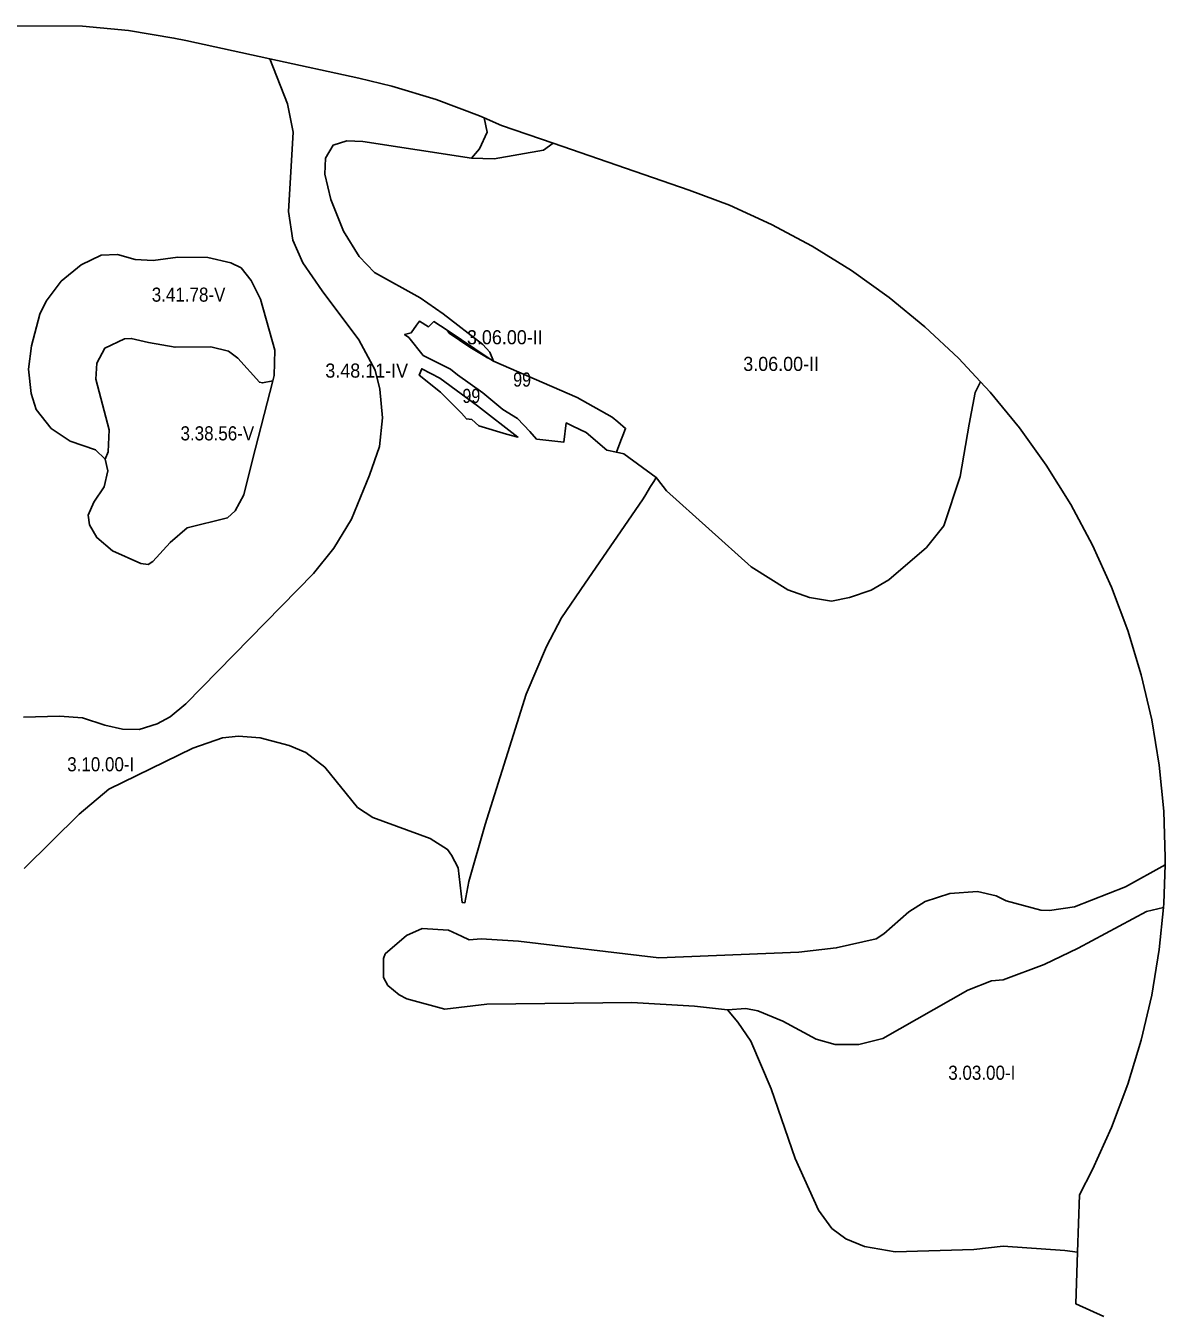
# Model space of a CAD drawing. Extents: x -591496 to -585489, y -1120610 to -1115685.
# Drawn here: x -587628 to -586013, y -1117681 to -1115858 of the extents above; entities that cross this region are included whole.
import ezdxf

# ---------------------------------------------------------------- set-up
doc = ezdxf.new("R2010")
doc.units = 0
doc.header["$LTSCALE"] = 8
doc.layers.add('40', color=7, linetype='Continuous', lineweight=25)
doc.layers.add('41', color=7, linetype='Continuous')

msp = doc.modelspace()

# ---------------------------------------------------------------- linework, layer by layer
at = {"layer": '40'}
for points in [[(-587669.707, -1115858.407), (-587547.277, -1115858.921), (-587482.154, -1115865.335), (-587417.59, -1115875.995), (-587400.616, -1115879.524), (-587281.831, -1115905.301), (-587256.5, -1115969), (-587248.5, -1116009), (-587255.5, -1116121.5), (-587249, -1116162), (-587235, -1116194.5), (-587207.5, -1116234), (-587155.5, -1116303.5), (-587132.5, -1116346.5), (-587126, -1116373.5), (-587122, -1116414), (-587126.5, -1116454.5), (-587140.5, -1116495), (-587166, -1116557.5), (-587191, -1116598.5), (-587220, -1116634.5), (-587400.5, -1116819), (-587423, -1116837.5), (-587441.5, -1116847.5), (-587467, -1116855.5), (-587490.5, -1116855), (-587515.5, -1116849.5), (-587547, -1116839), (-587579.5, -1116836.5), (-587630.5, -1116838)], [(-587630.5, -1116838), (-587579.5, -1116836.5), (-587547, -1116839), (-587515.5, -1116849.5), (-587490.5, -1116855), (-587467, -1116855.5), (-587441.5, -1116847.5), (-587423, -1116837.5), (-587400.5, -1116819), (-587220, -1116634.5), (-587191, -1116598.5), (-587166, -1116557.5), (-587140.5, -1116495), (-587126.5, -1116454.5), (-587122, -1116414), (-587126, -1116373.5), (-587132.5, -1116346.5), (-587155.5, -1116303.5), (-587207.5, -1116234), (-587235, -1116194.5), (-587249, -1116162), (-587255.5, -1116121.5), (-587248.5, -1116009), (-587256.5, -1115969), (-587281.831, -1115905.301), (-587155.546, -1115932.704), (-587108.791, -1115944.034), (-587046.171, -1115963.03), (-586984.927, -1115986.08), (-586978.084, -1115989.052)], [(-586978.084, -1115989.052), (-586974, -1116009), (-586984.5, -1116033), (-586996, -1116046), (-587150, -1116022.5), (-587172.5, -1116021.5), (-587192, -1116027.5), (-587203, -1116046), (-587204, -1116068.5), (-587195.5, -1116104.5), (-587177.5, -1116149.5), (-587155, -1116185.5), (-587133.5, -1116208), (-587069, -1116244), (-587036, -1116266.5), (-586980, -1116310), (-586970, -1116321), (-586965, -1116333.5), (-586970.814, -1116329.647), (-587030.734, -1116289.937), (-587049.5, -1116277.5), (-587057, -1116285), (-587069.491, -1116276.774), (-587073.83, -1116282.86), (-587081.42, -1116293.5), (-587090.886, -1116296.094), (-587085, -1116300), (-587064.5, -1116325.5), (-587026, -1116345), (-587016, -1116353), (-586980, -1116378.5), (-586951.5, -1116402), (-586931, -1116415), (-586913.5, -1116433.5), (-586903.859, -1116444.059), (-586903.36, -1116443.98), (-586865.12, -1116448.32), (-586861.84, -1116421.2), (-586852.47, -1116425.64), (-586833.76, -1116434.51), (-586804.158, -1116459.613), (-586790.752, -1116462.666), (-586780.5, -1116465), (-586734.5, -1116498.5), (-586734.516, -1116498.526), (-586734.47, -1116498.56), (-586737.85, -1116503.93), (-586742.49, -1116511.44), (-586750.68, -1116524.68), (-586753.92, -1116529.96), (-586753.992, -1116530.063), (-586754, -1116530), (-586835, -1116648), (-586868.5, -1116697.5), (-586890, -1116738), (-586918.5, -1116805.5), (-586931.5, -1116846), (-586976.5, -1116990), (-587000, -1117071), (-587005.5, -1117101), (-587009.5, -1117100.5), (-587015, -1117051.5), (-587024.5, -1117033.5), (-587030, -1117025.5), (-587054.5, -1117010), (-587136, -1116980), (-587157.5, -1116966), (-587204, -1116909), (-587230.5, -1116888), (-587254.5, -1116878), (-587295.5, -1116867.5), (-587326, -1116865), (-587349, -1116867.5), (-587391, -1116882), (-587510, -1116940), (-587552, -1116975.5), (-587629.5, -1117052.5)], [(-587629.5, -1117052.5), (-587552, -1116975.5), (-587510, -1116940), (-587391, -1116882), (-587349, -1116867.5), (-587326, -1116865), (-587295.5, -1116867.5), (-587254.5, -1116878), (-587230.5, -1116888), (-587204, -1116909), (-587157.5, -1116966), (-587136, -1116980), (-587054.5, -1117010), (-587030, -1117025.5), (-587024.5, -1117033.5), (-587015, -1117051.5), (-587009.5, -1117100.5), (-587005.5, -1117101), (-587000, -1117071), (-586976.5, -1116990), (-586931.5, -1116846), (-586918.5, -1116805.5), (-586890, -1116738), (-586868.5, -1116697.5), (-586835, -1116648), (-586754, -1116530), (-586753.992, -1116530.063), (-586753.92, -1116529.96), (-586750.68, -1116524.68), (-586742.49, -1116511.44), (-586737.85, -1116503.93), (-586734.47, -1116498.56), (-586732.764, -1116500.774), (-586720, -1116517.5), (-586600, -1116625), (-586548, -1116657.5), (-586517.5, -1116668.5), (-586486, -1116673.5), (-586460.5, -1116668.5), (-586430, -1116658), (-586405, -1116643.5), (-586351.5, -1116597.5), (-586327, -1116567), (-586304, -1116497), (-586291, -1116423), (-586282.5, -1116378), (-586274.887, -1116363.051), (-586261.49, -1116377.354), (-586219.977, -1116427.939), (-586181.86, -1116481.13), (-586147.305, -1116536.7), (-586116.457, -1116594.411), (-586089.45, -1116654.017)], [(-586089.45, -1116654.017), (-586066.4, -1116715.261), (-586047.404, -1116777.881), (-586032.545, -1116841.61), (-586021.885, -1116906.174), (-586015.471, -1116971.297), (-586013.33, -1117036.7), (-586013.668, -1117047.039), (-586069.5, -1117078.5), (-586142, -1117106.5), (-586177.5, -1117112), (-586189.5, -1117111.5), (-586238.5, -1117098), (-586253, -1117091), (-586279.5, -1117085), (-586318.5, -1117088), (-586353.5, -1117099), (-586376.5, -1117114), (-586412, -1117145), (-586423, -1117152), (-586479.5, -1117165), (-586532.5, -1117171), (-586730.5, -1117179), (-586929.5, -1117155.5), (-586982.5, -1117152), (-586999.5, -1117153.5), (-587010, -1117148.5), (-587028.5, -1117140), (-587066, -1117137.5), (-587088, -1117147.5), (-587118.5, -1117173.5), (-587120.5, -1117180), (-587120.5, -1117207), (-587114.5, -1117218), (-587098.5, -1117231.5), (-587087.5, -1117237), (-587034, -1117251.5), (-586974.5, -1117244.5), (-586769, -1117242.5), (-586680, -1117247.5), (-586633.5, -1117252.5), (-586619, -1117270), (-586600.5, -1117297), (-586571.5, -1117364.5), (-586537.5, -1117463.5), (-586504.5, -1117536.5), (-586485.5, -1117562.5), (-586466, -1117577), (-586439.5, -1117588), (-586396, -1117595.5), (-586284.5, -1117592), (-586243, -1117587.5), (-586155.5, -1117593.5), (-586137.593, -1117596.17), (-586139.893, -1117669.247), (-586100.231, -1117687.217)]]:
    msp.add_lwpolyline(points, dxfattribs=at)
for points in [[(-586894, -1116034.5), (-586964, -1116047), (-586996, -1116046), (-586984.5, -1116033), (-586974, -1116009), (-586978.084, -1115989.052), (-586953.803, -1115999.595), (-586880.366, -1116024.876)], [(-586996, -1116046), (-586964, -1116047), (-586894, -1116034.5), (-586880.366, -1116024.876), (-586687.823, -1116091.16), (-586630.647, -1116112.82), (-586571.041, -1116139.827), (-586513.33, -1116170.675), (-586457.76, -1116205.23), (-586404.569, -1116243.347), (-586353.984, -1116284.86), (-586306.223, -1116329.593), (-586274.887, -1116363.051), (-586282.5, -1116378), (-586291, -1116423), (-586304, -1116497), (-586327, -1116567), (-586351.5, -1116597.5), (-586405, -1116643.5), (-586430, -1116658), (-586460.5, -1116668.5), (-586486, -1116673.5), (-586517.5, -1116668.5), (-586548, -1116657.5), (-586600, -1116625), (-586720, -1116517.5), (-586732.764, -1116500.774), (-586734.47, -1116498.56), (-586734.516, -1116498.526), (-586734.5, -1116498.5), (-586780.5, -1116465), (-586790.752, -1116462.666), (-586784.4, -1116446.07), (-586781.73, -1116439.09), (-586777.85, -1116428.97), (-586788.76, -1116419.65), (-586796.586, -1116412.969), (-586846.5, -1116385), (-586965, -1116333.5), (-586970, -1116321), (-586980, -1116310), (-587036, -1116266.5), (-587069, -1116244), (-587133.5, -1116208), (-587155, -1116185.5), (-587177.5, -1116149.5), (-587195.5, -1116104.5), (-587204, -1116068.5), (-587203, -1116046), (-587192, -1116027.5), (-587172.5, -1116021.5), (-587150, -1116022.5)], [(-587277.449, -1116361.513), (-587292, -1116364.5), (-587296.5, -1116363.5), (-587327, -1116329.5), (-587340.5, -1116319.5), (-587365.5, -1116313.5), (-587416, -1116314), (-587453.5, -1116307), (-587478, -1116301.5), (-587487.5, -1116302), (-587515.5, -1116315), (-587527, -1116336.5), (-587528, -1116359), (-587509.5, -1116431), (-587510.5, -1116462), (-587515, -1116472.5), (-587528.5, -1116459.5), (-587564.5, -1116447), (-587591.5, -1116429), (-587612.5, -1116402), (-587620, -1116379.5), (-587623.5, -1116345), (-587619.5, -1116312), (-587607.5, -1116267), (-587598.5, -1116248.5), (-587577.5, -1116220.5), (-587549, -1116197), (-587520.5, -1116183.5), (-587497.5, -1116182.5), (-587472.5, -1116189.5), (-587447, -1116191), (-587412, -1116186.5), (-587369.5, -1116187), (-587337, -1116194.5), (-587322.5, -1116201.5), (-587308, -1116219.5), (-587295, -1116246), (-587274.5, -1116318), (-587275.5, -1116354)], [(-587515, -1116472.5), (-587511, -1116489), (-587516.5, -1116511.5), (-587531, -1116533.5), (-587539, -1116552), (-587537, -1116565.5), (-587527, -1116583.5), (-587504.5, -1116602.5), (-587464.5, -1116620.5), (-587454, -1116621.5), (-587447.5, -1116617.5), (-587423, -1116590.5), (-587399, -1116570), (-587341.5, -1116555.5), (-587331, -1116545.5), (-587318.5, -1116523), (-587306.5, -1116473.5), (-587277.449, -1116361.513), (-587275.5, -1116354), (-587274.5, -1116318), (-587295, -1116246), (-587308, -1116219.5), (-587322.5, -1116201.5), (-587337, -1116194.5), (-587369.5, -1116187), (-587412, -1116186.5), (-587447, -1116191), (-587472.5, -1116189.5), (-587497.5, -1116182.5), (-587520.5, -1116183.5), (-587549, -1116197), (-587577.5, -1116220.5), (-587598.5, -1116248.5), (-587607.5, -1116267), (-587619.5, -1116312), (-587623.5, -1116345), (-587620, -1116379.5), (-587612.5, -1116402), (-587591.5, -1116429), (-587564.5, -1116447), (-587528.5, -1116459.5)], [(-587030.734, -1116289.937), (-587027.6, -1116293.87), (-586998.64, -1116313.66), (-586977.3, -1116326.58), (-586974.31, -1116328.39), (-586970.814, -1116329.647), (-586965, -1116333.5), (-586846.5, -1116385), (-586796.586, -1116412.969), (-586788.76, -1116419.65), (-586777.85, -1116428.97), (-586781.73, -1116439.09), (-586784.4, -1116446.07), (-586790.752, -1116462.666), (-586804.158, -1116459.613), (-586833.76, -1116434.51), (-586852.47, -1116425.64), (-586861.84, -1116421.2), (-586865.12, -1116448.32), (-586903.36, -1116443.98), (-586903.859, -1116444.059), (-586913.5, -1116433.5), (-586931, -1116415), (-586951.5, -1116402), (-586980, -1116378.5), (-587016, -1116353), (-587026, -1116345), (-587064.5, -1116325.5), (-587085, -1116300), (-587090.886, -1116296.094), (-587081.42, -1116293.5), (-587073.83, -1116282.86), (-587069.491, -1116276.774), (-587057, -1116285), (-587049.5, -1116277.5)], [(-586970.814, -1116329.647), (-586974.31, -1116328.39), (-586977.3, -1116326.58), (-586998.64, -1116313.66), (-587027.6, -1116293.87), (-587030.734, -1116289.937)], [(-587277.449, -1116361.513), (-587306.5, -1116473.5), (-587318.5, -1116523), (-587331, -1116545.5), (-587341.5, -1116555.5), (-587399, -1116570), (-587423, -1116590.5), (-587447.5, -1116617.5), (-587454, -1116621.5), (-587464.5, -1116620.5), (-587504.5, -1116602.5), (-587527, -1116583.5), (-587537, -1116565.5), (-587539, -1116552), (-587531, -1116533.5), (-587516.5, -1116511.5), (-587511, -1116489), (-587515, -1116472.5), (-587510.5, -1116462), (-587509.5, -1116431), (-587528, -1116359), (-587527, -1116336.5), (-587515.5, -1116315), (-587487.5, -1116302), (-587478, -1116301.5), (-587453.5, -1116307), (-587416, -1116314), (-587365.5, -1116313.5), (-587340.5, -1116319.5), (-587327, -1116329.5), (-587296.5, -1116363.5), (-587292, -1116364.5)], [(-586987.5, -1116397), (-586930.248, -1116441.141), (-586946.45, -1116437.07), (-586985.85, -1116425.16), (-586995.72, -1116416.27), (-587003.225, -1116415.384), (-587010, -1116407.5), (-587022, -1116395.5), (-587040, -1116377.5), (-587070, -1116353.5), (-587066.5, -1116344.5), (-587041, -1116357.5)], [(-586987.5, -1116397), (-587041, -1116357.5), (-587066.5, -1116344.5), (-587070, -1116353.5), (-587040, -1116377.5), (-587022, -1116395.5), (-587010, -1116407.5), (-587003.225, -1116415.384), (-586995.72, -1116416.27), (-586985.85, -1116425.16), (-586946.45, -1116437.07), (-586930.248, -1116441.141)], [(-586015.997, -1117107.443), (-586040, -1117113.5), (-586136.5, -1117165.5), (-586185, -1117188.5), (-586243, -1117210), (-586259.5, -1117211.5), (-586293, -1117225), (-586413.5, -1117293.5), (-586447.5, -1117302), (-586481, -1117302), (-586508, -1117294), (-586555, -1117268.5), (-586590.5, -1117254), (-586607.5, -1117251), (-586633.5, -1117252.5), (-586680, -1117247.5), (-586769, -1117242.5), (-586974.5, -1117244.5), (-587034, -1117251.5), (-587087.5, -1117237), (-587098.5, -1117231.5), (-587114.5, -1117218), (-587120.5, -1117207), (-587120.5, -1117180), (-587118.5, -1117173.5), (-587088, -1117147.5), (-587066, -1117137.5), (-587028.5, -1117140), (-587010, -1117148.5), (-586999.5, -1117153.5), (-586982.5, -1117152), (-586929.5, -1117155.5), (-586730.5, -1117179), (-586532.5, -1117171), (-586479.5, -1117165), (-586423, -1117152), (-586412, -1117145), (-586376.5, -1117114), (-586353.5, -1117099), (-586318.5, -1117088), (-586279.5, -1117085), (-586253, -1117091), (-586238.5, -1117098), (-586189.5, -1117111.5), (-586177.5, -1117112), (-586142, -1117106.5), (-586069.5, -1117078.5), (-586013.668, -1117047.039), (-586015.471, -1117102.103)], [(-586137.593, -1117596.17), (-586155.5, -1117593.5), (-586243, -1117587.5), (-586284.5, -1117592), (-586396, -1117595.5), (-586439.5, -1117588), (-586466, -1117577), (-586485.5, -1117562.5), (-586504.5, -1117536.5), (-586537.5, -1117463.5), (-586571.5, -1117364.5), (-586600.5, -1117297), (-586619, -1117270), (-586633.5, -1117252.5), (-586607.5, -1117251), (-586590.5, -1117254), (-586555, -1117268.5), (-586508, -1117294), (-586481, -1117302), (-586447.5, -1117302), (-586413.5, -1117293.5), (-586293, -1117225), (-586259.5, -1117211.5), (-586243, -1117210), (-586185, -1117188.5), (-586136.5, -1117165.5), (-586040, -1117113.5), (-586015.997, -1117107.443), (-586021.885, -1117167.226), (-586032.545, -1117231.79), (-586047.404, -1117295.519), (-586066.4, -1117358.139), (-586089.45, -1117419.383), (-586116.457, -1117478.989), (-586116.462, -1117478.997), (-586135.024, -1117514.545)]]:
    msp.add_lwpolyline(points, close=True, dxfattribs=at)

# ---------------------------------------------------------------- texts
at = {"layer": '41'}
for s, width, p in [('3.41.78-V', 0.9, (-587449, -1116249.375)), ('3.06.00-II', 0.95, (-587002.531, -1116309.75)), ('3.06.00-II', 0.95, (-586611.125, -1116347.5)), ('3.48.11-IV', 0.95, (-587203.125, -1116357)), ('99', 0.85, (-586937.031, -1116369.75)), ('99', 0.85, (-587008.938, -1116392.875)), ('3.38.56-V', 0.9, (-587408.25, -1116445.875)), ('3.10.00-I', 0.9, (-587568.75, -1116914.75)), ('3.03.00-I', 0.9, (-586320.719, -1117351.75))]:
    msp.add_text(s, height=20, dxfattribs=dict(at, width=width)).set_placement(p)

doc.saveas('drawing.dxf')
